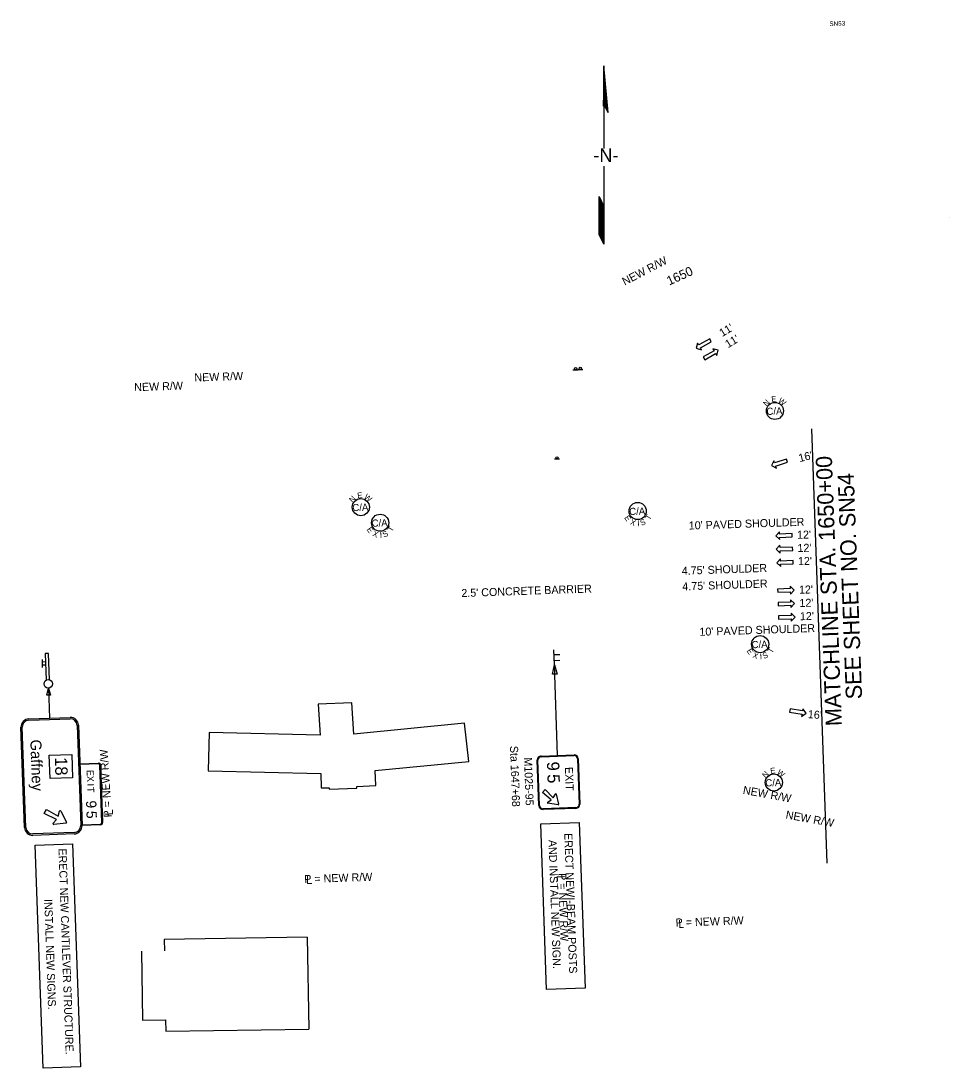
# Model space of a CAD drawing. Extents: x 1810445 to 1812085, y 1189733 to 1190648.
# Drawn here: x 1811273 to 1812085, y 1189733 to 1190648 of the extents above; entities that cross this region are included whole.
import ezdxf

# ---------------------------------------------------------------- set-up
doc = ezdxf.new("R2010")
doc.units = 0
for name, color, linetype in [('RD_EX_Bldg', 7, 'Continuous'), ('RD_HC_TX_Rel_Sta50', 7, 'Continuous'), ('RD_PD_Final_LnLine', 7, 'Continuous'), ('RD_PD_Final_TX', 7, 'Continuous'), ('RD_PD_RW_TX', 7, 'Continuous'), ('RD_SHT_MatchLine', 7, 'Continuous'), ('RD_SHT_TX', 7, 'Continuous'), ('RD_Sketch1', 7, 'Continuous'), ('RD_Sketch10', 7, 'Continuous'), ('RD_Sketch8', 7, 'Continuous'), ('SN_P_Signs', 7, 'Continuous')]:
    doc.layers.add(name, color=color, linetype=linetype)

# ---------------------------------------------------------------- blocks, each defined once
blk = doc.blocks.new('SARRW2')
at = {"layer": 'RD_PD_Final_LnLine'}
blk.add_lwpolyline([(-12, 1.2), (-12, -1.2), (-2.83, -1.2), (-2.83, -2.83), (0, 0), (-2.83, 2.83), (-2.83, 1.2)], close=True, dxfattribs=at)

msp = doc.modelspace()

# ---------------------------------------------------------------- linework, layer by layer
at = {"layer": 'RD_EX_Bldg'}
msp.add_line((1811523.34, 1189847.12), (1811524.64, 1189766.84), dxfattribs=at)
for points in [[(1811437.59, 1190026.22), (1811436.73, 1189992.78), (1811535.24, 1189990.39), (1811535.56, 1189977.65), (1811542.53, 1189977.83), (1811542.51, 1189976.65), (1811566.83, 1189977.48), (1811566.79, 1189978.85), (1811583.46, 1189979.69), (1811582.85, 1189992.97), (1811664.64, 1190000.77), (1811660.98, 1190034.2), (1811564.14, 1190024.8), (1811562.43, 1190052.15), (1811533.06, 1190050.93), (1811534.67, 1190023.71), (1811437.59, 1190026.22)], [(1811523.38, 1189847.12), (1811398.38, 1189845.25), (1811398.59, 1189835.31)], [(1811378.43, 1189835.01), (1811379.44, 1189774.7), (1811399.45, 1189774.94), (1811399.67, 1189764.99), (1811524.71, 1189766.84)]]:
    msp.add_lwpolyline(points, dxfattribs=at)
at = {"layer": 'RD_SHT_MatchLine'}
msp.add_line((1811964.42, 1190291.88), (1811977.81, 1189911.94), dxfattribs=at)
at = {"layer": 'RD_Sketch1'}
for p, q in [((1811782.8, 1190609.11), (1811782.59, 1190573.94)), ((1811786.52, 1190568.41), (1811782.8, 1190609.11)), ((1811782.8, 1190574.24), (1811782.8, 1190552.42)), ((1811783.1, 1190575.35), (1811786.52, 1190568.41)), ((1811782.8, 1190552.42), (1811782.8, 1190536.94)), ((1811782.8, 1190521.5), (1811782.8, 1190495.72)), ((1811778.81, 1190480.66), (1811778.81, 1190494.84)), ((1811778.81, 1190494.84), (1811782.8, 1190486.27)), ((1811782.8, 1190495.72), (1811782.8, 1190453.2)), ((1811778.81, 1190461.77), (1811778.81, 1190480.66)), ((1811782.8, 1190453.2), (1811778.81, 1190461.77))]:
    msp.add_line(p, q, dxfattribs=at)
for points in [[(1811782.81, 1190574.55), (1811782.81, 1190608.99)], [(1811782.9, 1190574.81), (1811782.9, 1190607.95)], [(1811783, 1190575.07), (1811783, 1190606.92)], [(1811783.09, 1190575.33), (1811783.09, 1190605.89)], [(1811783.19, 1190575.17), (1811783.19, 1190604.86)], [(1811783.28, 1190574.98), (1811783.28, 1190603.82)], [(1811783.38, 1190574.79), (1811783.38, 1190602.79)], [(1811783.47, 1190574.6), (1811783.47, 1190601.76)], [(1811783.57, 1190574.41), (1811783.57, 1190600.73)], [(1811783.66, 1190574.21), (1811783.66, 1190599.69)], [(1811783.76, 1190574.02), (1811783.76, 1190598.66)], [(1811783.85, 1190573.83), (1811783.85, 1190597.63)], [(1811782.72, 1190574.29), (1811782.72, 1190595.07)], [(1811783.94, 1190573.64), (1811783.94, 1190596.6)], [(1811784.04, 1190573.45), (1811784.04, 1190595.56)], [(1811784.13, 1190573.26), (1811784.13, 1190594.53)], [(1811784.23, 1190573.06), (1811784.23, 1190593.5)], [(1811784.32, 1190572.87), (1811784.32, 1190592.47)], [(1811784.42, 1190572.68), (1811784.42, 1190591.43)], [(1811784.51, 1190572.49), (1811784.51, 1190590.4)], [(1811784.61, 1190572.3), (1811784.61, 1190589.37)], [(1811784.7, 1190572.11), (1811784.7, 1190588.34)], [(1811782.62, 1190574.03), (1811782.62, 1190579.17)], [(1811784.79, 1190571.91), (1811784.79, 1190587.3)], [(1811784.89, 1190571.72), (1811784.89, 1190586.27)], [(1811784.98, 1190571.53), (1811784.98, 1190585.24)], [(1811785.08, 1190571.34), (1811785.08, 1190584.21)], [(1811785.17, 1190571.15), (1811785.17, 1190583.17)], [(1811785.27, 1190570.96), (1811785.27, 1190582.14)], [(1811785.36, 1190570.76), (1811785.36, 1190581.11)], [(1811785.46, 1190570.57), (1811785.46, 1190580.08)], [(1811785.55, 1190570.38), (1811785.55, 1190579.04)], [(1811785.64, 1190570.19), (1811785.64, 1190578.01)], [(1811785.74, 1190570), (1811785.74, 1190576.98)], [(1811785.83, 1190569.81), (1811785.83, 1190575.95)], [(1811785.93, 1190569.61), (1811785.93, 1190574.91)], [(1811786.02, 1190569.42), (1811786.02, 1190573.88)], [(1811786.12, 1190569.23), (1811786.12, 1190572.85)], [(1811786.21, 1190569.04), (1811786.21, 1190571.82)], [(1811786.31, 1190568.85), (1811786.31, 1190570.78)], [(1811786.4, 1190568.66), (1811786.4, 1190569.75)], [(1811786.5, 1190568.46), (1811786.5, 1190568.72)], [(1811778.88, 1190461.6), (1811778.88, 1190494.67)], [(1811778.98, 1190461.4), (1811778.98, 1190494.47)], [(1811779.07, 1190461.2), (1811779.07, 1190494.27)], [(1811779.17, 1190460.99), (1811779.17, 1190494.06)], [(1811779.26, 1190460.79), (1811779.26, 1190493.86)], [(1811779.36, 1190460.59), (1811779.36, 1190493.66)], [(1811779.45, 1190460.39), (1811779.45, 1190493.46)], [(1811779.54, 1190460.18), (1811779.54, 1190493.25)], [(1811779.64, 1190459.98), (1811779.64, 1190493.05)], [(1811779.73, 1190459.78), (1811779.73, 1190492.85)], [(1811779.83, 1190459.58), (1811779.83, 1190492.65)], [(1811779.92, 1190459.37), (1811779.92, 1190492.44)], [(1811780.02, 1190459.17), (1811780.02, 1190492.24)], [(1811780.11, 1190458.97), (1811780.11, 1190492.04)], [(1811780.21, 1190458.76), (1811780.21, 1190491.84)], [(1811780.3, 1190458.56), (1811780.3, 1190491.63)], [(1811780.39, 1190458.36), (1811780.39, 1190491.43)], [(1811780.49, 1190458.16), (1811780.49, 1190491.23)], [(1811780.58, 1190457.95), (1811780.58, 1190491.02)], [(1811780.68, 1190457.75), (1811780.68, 1190490.82)], [(1811780.77, 1190457.55), (1811780.77, 1190490.62)], [(1811780.87, 1190457.35), (1811780.87, 1190490.42)], [(1811780.96, 1190457.14), (1811780.96, 1190490.21)], [(1811781.06, 1190456.94), (1811781.06, 1190490.01)], [(1811781.15, 1190456.74), (1811781.15, 1190489.81)], [(1811781.24, 1190456.54), (1811781.24, 1190489.61)], [(1811781.34, 1190456.33), (1811781.34, 1190489.4)], [(1811781.43, 1190456.13), (1811781.43, 1190489.2)], [(1811781.53, 1190455.93), (1811781.53, 1190489)], [(1811781.62, 1190455.73), (1811781.62, 1190488.8)], [(1811781.72, 1190455.52), (1811781.72, 1190488.59)], [(1811781.81, 1190455.32), (1811781.81, 1190488.39)], [(1811781.91, 1190455.12), (1811781.91, 1190488.19)], [(1811782, 1190454.91), (1811782, 1190487.99)], [(1811782.1, 1190454.71), (1811782.1, 1190487.78)], [(1811782.19, 1190454.51), (1811782.19, 1190487.58)], [(1811782.28, 1190454.31), (1811782.28, 1190487.38)], [(1811782.38, 1190454.1), (1811782.38, 1190487.17)], [(1811782.47, 1190453.9), (1811782.47, 1190486.97)], [(1811782.57, 1190453.7), (1811782.57, 1190486.77)], [(1811782.66, 1190453.5), (1811782.66, 1190486.57)], [(1811782.76, 1190453.29), (1811782.76, 1190486.36)]]:
    msp.add_lwpolyline(points, dxfattribs=at)
at = {"layer": 'RD_Sketch10'}
for centre in [(1811932.4, 1190307.41), (1811570.25, 1190223.24), (1811931.42, 1189982.47)]:
    msp.add_circle(centre, 7.5, dxfattribs=at)
at = {"layer": 'RD_Sketch8'}
for centre in [(1811812.41, 1190219.82), (1811587.11, 1190209.61), (1811919.45, 1190103.37)]:
    msp.add_circle(centre, 7.5, dxfattribs=at)
at = {"layer": 'SN_P_Signs'}
for p, q in [((1812084.7, 1190476.58), (1812084.7, 1190476.58)), ((1811755.78, 1190343.4), (1811760.28, 1190343.4)), ((1811759.92, 1190343.58), (1811764.42, 1190343.58)), ((1811739.5, 1190265.36), (1811744, 1190265.36)), ((1811739.55, 1190085.36), (1811739.09, 1190098.4)), ((1811739.24, 1190094.29), (1811744.22, 1190094.46)), ((1811291.98, 1190082.96), (1811291.73, 1190089.91)), ((1811294.56, 1190087.83), (1811291.79, 1190087.73)), ((1811294.66, 1190085.15), (1811291.89, 1190085.05)), ((1811739.41, 1190089.27), (1811744.4, 1190089.45)), ((1811742.34, 1190006.11), (1811739.55, 1190085.36)), ((1811296.99, 1190065.02), (1811297.92, 1190038.78)), ((1811297.68, 1190006.3), (1811317.36, 1190006.99)), ((1811298.4, 1189985.83), (1811297.68, 1190006.3)), ((1811317.36, 1190006.99), (1811318.08, 1189986.52)), ((1811725.88, 1189962.3), (1811724.48, 1190001.88)), ((1811726.48, 1189962.32), (1811725.08, 1190001.9)), ((1811727.95, 1190005.6), (1811756.74, 1190006.62)), ((1811727.97, 1190005), (1811756.76, 1190006.02)), ((1811759.86, 1190003.12), (1811761.26, 1189963.55)), ((1811760.46, 1190003.14), (1811761.85, 1189963.57)), ((1811318.08, 1189986.52), (1811298.4, 1189985.83)), ((1811758.36, 1189960.44), (1811729.58, 1189959.43)), ((1811758.38, 1189959.84), (1811729.6, 1189958.83)), ((1811727.63, 1189946.39), (1811761.23, 1189947.57)), ((1811761.23, 1189947.57), (1811766.33, 1189802.64)), ((1811732.74, 1189801.46), (1811727.63, 1189946.39)), ((1811285.42, 1189927.58), (1811318.21, 1189928.74)), ((1811318.21, 1189928.74), (1811325.08, 1189733.86)), ((1811292.29, 1189732.7), (1811285.42, 1189927.58)), ((1811766.33, 1189802.64), (1811732.74, 1189801.46)), ((1811325.08, 1189733.86), (1811292.29, 1189732.7))]:
    msp.add_line(p, q, dxfattribs=at)
for points in [[(1811297.9, 1190072.29), (1811297.09, 1190095.4), (1811294.3, 1190095.3), (1811295.12, 1190072)], [(1811279.93, 1190038.15), (1811315.91, 1190039.41)], [(1811276.07, 1189943.15), (1811272.99, 1190030.7)], [(1811277.27, 1189943.19), (1811274.19, 1190030.74)], [(1811279.97, 1190036.95), (1811315.95, 1190038.21)], [(1811322.16, 1190032.43), (1811325.24, 1189944.88)], [(1811323.36, 1190032.47), (1811326.44, 1189944.93)], [(1811340.75, 1189998.86), (1811324.56, 1189998.29), (1811324.54, 1189998.89), (1811340.73, 1189999.46)], [(1811343.77, 1189947.34), (1811341.99, 1189997.71)], [(1811342.59, 1189997.73), (1811344.37, 1189947.36)], [(1811729.08, 1189973.69), (1811731.53, 1189976.32), (1811738.58, 1189969.14)], [(1811736.74, 1189967.17), (1811729.08, 1189973.69)], [(1811733.66, 1189965.16), (1811736.74, 1189967.17)], [(1811738.58, 1189969.14), (1811740.36, 1189972.36)], [(1811741.19, 1189972.24), (1811743.25, 1189963.45)], [(1811293.36, 1189955.26), (1811295.34, 1189958.97), (1811305.57, 1189952.98)], [(1811305.57, 1189952.98), (1811306.69, 1189957.28)], [(1811307.8, 1189957.42), (1811312.89, 1189947.83)], [(1811742.74, 1189962.9), (1811733.83, 1189964.34)], [(1811304.06, 1189950.13), (1811293.36, 1189955.26)], [(1811301.12, 1189946.8), (1811304.06, 1189950.13)], [(1811312.43, 1189946.95), (1811301.63, 1189945.81)], [(1811319.46, 1189938.68), (1811283.48, 1189937.41)], [(1811326.42, 1189945.53), (1811342.61, 1189946.1)], [(1811342.63, 1189945.5), (1811326.44, 1189944.93), (1811326.42, 1189945.53)], [(1811319.5, 1189937.48), (1811283.52, 1189936.21)]]:
    msp.add_lwpolyline(points, dxfattribs=at)
for points in [[(1811737.79, 1190077.09), (1811739.55, 1190085.36), (1811741.89, 1190077.24)], [(1811295.67, 1190058.81), (1811296.99, 1190065.02), (1811298.75, 1190058.92)]]:
    msp.add_lwpolyline(points, close=True, dxfattribs=at)
for centre, radius in [((1811758.04, 1190344.41), 1), ((1811762.18, 1190344.59), 1), ((1811741.76, 1190266.37), 1), ((1811296.86, 1190068.72), 3.71)]:
    msp.add_circle(centre, radius, dxfattribs=at)
for centre, radius, start, end in [((1811316.16, 1190032.22), 7.2, 2.01838, 92.01838), ((1811280.18, 1190030.95), 7.2, 92.01838, 182.01838), ((1811280.18, 1190030.95), 6, 92.01838, 182.01838), ((1811316.16, 1190032.22), 6, 2.01838, 92.01838), ((1811728.08, 1190002), 3.6, 92.01838, 182.01838), ((1811728.08, 1190002), 3, 92.01838, 182.01838), ((1811756.86, 1190003.02), 3.6, 2.01838, 92.01838), ((1811756.86, 1190003.02), 3, 2.01838, 92.01838), ((1811340.79, 1189997.66), 1.8, 2.01838, 92.01838), ((1811340.79, 1189997.66), 1.2, 2.01838, 92.01838), ((1811733.9, 1189964.78), 0.45, 123.05628, 260.84048), ((1811740.75, 1189972.14), 0.45, 13.19628, 150.98048), ((1811307.27, 1189957.13), 0.6, 27.99908, 165.46448), ((1811729.47, 1189962.43), 3.6, 182.01838, 272.01838), ((1811729.47, 1189962.43), 3, 182.01838, 272.01838), ((1811742.81, 1189963.35), 0.45, 260.84048, 13.19628), ((1811758.26, 1189963.44), 3, 272.01838, 2.01838), ((1811758.26, 1189963.44), 3.6, 272.01838, 2.01838), ((1811312.36, 1189947.55), 0.6, 276.03778, 27.99908), ((1811342.57, 1189947.3), 1.2, 272.01838, 2.01838), ((1811342.57, 1189947.3), 1.8, 272.01838, 2.01838), ((1811283.27, 1189943.4), 7.2, 182.01838, 272.01838), ((1811283.27, 1189943.4), 6, 182.01838, 272.01838), ((1811301.57, 1189946.4), 0.6, 138.57228, 276.03778), ((1811319.25, 1189944.67), 6, 272.01838, 2.01838), ((1811319.25, 1189944.67), 7.2, 272.01838, 2.01838)]:
    msp.add_arc(centre, radius, start, end, dxfattribs=at)

# ---------------------------------------------------------------- block references
at = {"layer": 'RD_PD_Final_LnLine'}
for p, xscale, yscale, rotation in [((1811863.5, 1190362.15), 1.1999999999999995, 1.2000000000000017, -150.71986908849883), ((1811882.82, 1190360.47), 1.1999999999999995, 1.2000000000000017, 29.28013091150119), ((1811929.37, 1190259.53), 1.1999999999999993, 1.200000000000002, -162.37812260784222), ((1811933.1, 1190198.14), 1.1999999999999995, 1.2000000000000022, -177.9816202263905), ((1811933.51, 1190186.36), 1.1999999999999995, 1.2000000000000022, -177.9816202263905), ((1811933.93, 1190174.58), 1.1999999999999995, 1.2000000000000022, -177.9816202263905), ((1811949.18, 1190150.73), 1.1999999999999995, 1.2000000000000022, 2.018379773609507), ((1811949.59, 1190138.95), 1.1999999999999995, 1.2000000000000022, 2.018379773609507), ((1811950.01, 1190127.17), 1.1999999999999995, 1.2000000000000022, 2.018379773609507), ((1811959.69, 1190042.99), 1.1999999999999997, 1.2000000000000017, -9.803136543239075)]:
    msp.add_blockref('SARRW2', p, dxfattribs=dict(at, xscale=xscale, yscale=yscale, rotation=rotation))

# ---------------------------------------------------------------- texts
at = {"layer": 'RD_HC_TX_Rel_Sta50'}
msp.add_text('1650', height=8, rotation=24.41001, dxfattribs=at).set_placement((1811839.94, 1190416.99))
at = {"layer": 'RD_PD_Final_TX'}
for s, rotation, p in [("11'", 30.93964, (1811886.33, 1190371.95)), ("11'", 30.93964, (1811891.37, 1190362.19)), ("16'", 14.04474, (1811954, 1190262.55)), ("10' PAVED SHOULDER", 1.90447, (1811857.16, 1190203.63)), ("12'", 1.39156, (1811951.83, 1190195.53)), ("12'", 1.39156, (1811952.24, 1190184.01)), ("12'", 1.39156, (1811952.65, 1190172.49)), ("4.75' SHOULDER", 2.01838, (1811851.05, 1190164.05)), ("4.75' SHOULDER", 2.01838, (1811851.53, 1190150.39)), ("2.5' CONCRETE BARRIER", 2.02012, (1811658.27, 1190144.58)), ("12'", 1.39156, (1811953.53, 1190147.52)), ("12'", 1.39156, (1811953.93, 1190135.93)), ("12'", 1.39156, (1811954.34, 1190124.34)), ("10' PAVED SHOULDER", 1.90447, (1811866.48, 1190110.68)), ("16'", 355.71174, (1811961.02, 1190038.79)), ('P = NEW R/W', 93.49537, (1811352.42, 1189952.1)), ('L', 93.49537, (1811353.65, 1189953.89)), ('P = NEW R/W', 1.91192, (1811520.88, 1189894.48)), ('P = NEW R/W', 271.91192, (1811742.85, 1189903.02)), ('L', 1.91192, (1811522.55, 1189893.59)), ('L', 271.91192, (1811741.48, 1189901.09)), ('P = NEW R/W', 1.91192, (1811845.67, 1189856.44)), ('L', 1.91192, (1811848.02, 1189855.21))]:
    msp.add_text(s, height=7, rotation=rotation, dxfattribs=at).set_placement(p)
at = {"layer": 'RD_PD_RW_TX'}
for rotation, p in [(27.49969, (1811801.04, 1190416.98)), (1.89429, (1811424.77, 1190333.11)), (1.89429, (1811372.17, 1190324.66)), (349.60289, (1811904.02, 1189972.67)), (349.60289, (1811941.44, 1189951.09))]:
    msp.add_text('NEW R/W', height=7, rotation=rotation, dxfattribs=at).set_placement(p)
at = {"layer": 'RD_SHT_TX'}
for s, height, rotation, p in [('SN53', 4, 2.01838, (1811980.09, 1190643.96)), ('MATCHLINE STA. 1650+00 ', 14.1726, 92.14236, (1811990.99, 1190032)), ('SEE SHEET NO. SN54', 14.1726, 92.14236, (1812008.7, 1190055.43))]:
    msp.add_text(s, height=height, rotation=rotation, dxfattribs=at).set_placement(p)
at = {"layer": 'RD_Sketch1'}
msp.add_text('-N-', height=11.811, rotation=0, dxfattribs=at).set_placement((1811773.6, 1190525.21))
at = {"layer": 'RD_Sketch10'}
for s, height, rotation, p in [('N', 5, 46.88815, (1811925.15, 1190310.99)), ('E', 5, 6.35143, (1811929.57, 1190315.02)), ('W', 5, 321.321, (1811934.74, 1190315.45)), ('C/A', 6.25, 2.01838, (1811925.11, 1190303.87)), ('N', 5, 46.88815, (1811563, 1190226.82)), ('E', 5, 6.35143, (1811567.42, 1190230.85)), ('W', 5, 321.321, (1811572.59, 1190231.28)), ('C/A', 6.25, 2.01838, (1811562.96, 1190219.7)), ('E', 5, 6.35143, (1811928.58, 1189990.08)), ('W', 5, 321.321, (1811933.76, 1189990.51)), ('N', 5, 46.88815, (1811924.16, 1189986.05)), ('C/A', 6.25, 2.01838, (1811924.13, 1189978.93))]:
    msp.add_text(s, height=height, rotation=rotation, dxfattribs=at).set_placement(p)
at = {"layer": 'RD_Sketch8'}
for s, height, rotation, p in [('C/A', 6.25, 2.01838, (1811805.11, 1190216.29)), ('C/A', 6.25, 2.01838, (1811579.81, 1190206.07)), ('E', 5, 305.22962, (1811800.39, 1190213.88)), ('X', 5, 337.659, (1811805.36, 1190208.39)), ('S', 5, 23.81082, (1811815.86, 1190206.86)), ('T', 5, 60.20353, (1811822.9, 1190211.48)), ('E', 5, 305.22962, (1811575.09, 1190203.66)), ('T', 5, 60.20353, (1811597.6, 1190201.27)), ('I', 5, 1.819, (1811812.21, 1190206.56)), ('X', 5, 337.659, (1811580.06, 1190198.18)), ('I', 5, 1.819, (1811586.92, 1190196.35)), ('S', 5, 23.81082, (1811590.56, 1190196.65)), ('C/A', 6.25, 2.01838, (1811912.16, 1190099.84)), ('E', 5, 305.22962, (1811907.43, 1190097.43)), ('X', 5, 337.659, (1811912.41, 1190091.94)), ('I', 5, 1.819, (1811919.26, 1190090.11)), ('S', 5, 23.81082, (1811922.9, 1190090.41)), ('T', 5, 60.20353, (1811929.94, 1190095.03))]:
    msp.add_text(s, height=height, rotation=rotation, dxfattribs=at).set_placement(p)
at = {"layer": 'SN_P_Signs'}
for s, height, rotation, p in [('Gaffney', 9.6, 272.01838, (1811281.17, 1190019.84)), ('Sta 1647+68', 7, 272.01846, (1811700.71, 1190014.37)), ('18', 10.8, 272.01838, (1811302.58, 1190004.43)), ('M1025-95', 7, 272.01846, (1811712.97, 1190004.27)), ('E', 6, 272.01838, (1811330.44, 1189993.36)), ('9', 10.8, 272.01838, (1811732.94, 1190000.5)), ('EXIT', 7, 272.01838, (1811748.71, 1189995.92)), ('X', 6, 272.01838, (1811330.62, 1189988.21)), ('5', 10.8, 272.01838, (1811733.32, 1189989.58)), ('I', 6, 272.01838, (1811330.86, 1189981.4)), ('T', 6, 272.01838, (1811330.96, 1189978.42)), ('9', 9, 272.01838, (1811329.88, 1189966.51)), ('5', 9, 272.01838, (1811330.2, 1189957.41)), ('AND INSTALL NEW SIGN.', 6.9998, 272.01846, (1811734.39, 1189932.19)), ('ERECT NEWI-BEAM POSTS', 6.9998, 272.01846, (1811748.19, 1189938.02)), ('ERECT NEW CANTILEVER STRUCTURE.', 7, 272.01846, (1811305.8, 1189924.66)), ('INSTALL NEW SIGNS.', 7, 272.01846, (1811293.35, 1189880.45))]:
    msp.add_text(s, height=height, rotation=rotation, dxfattribs=at).set_placement(p)

doc.saveas('drawing.dxf')
